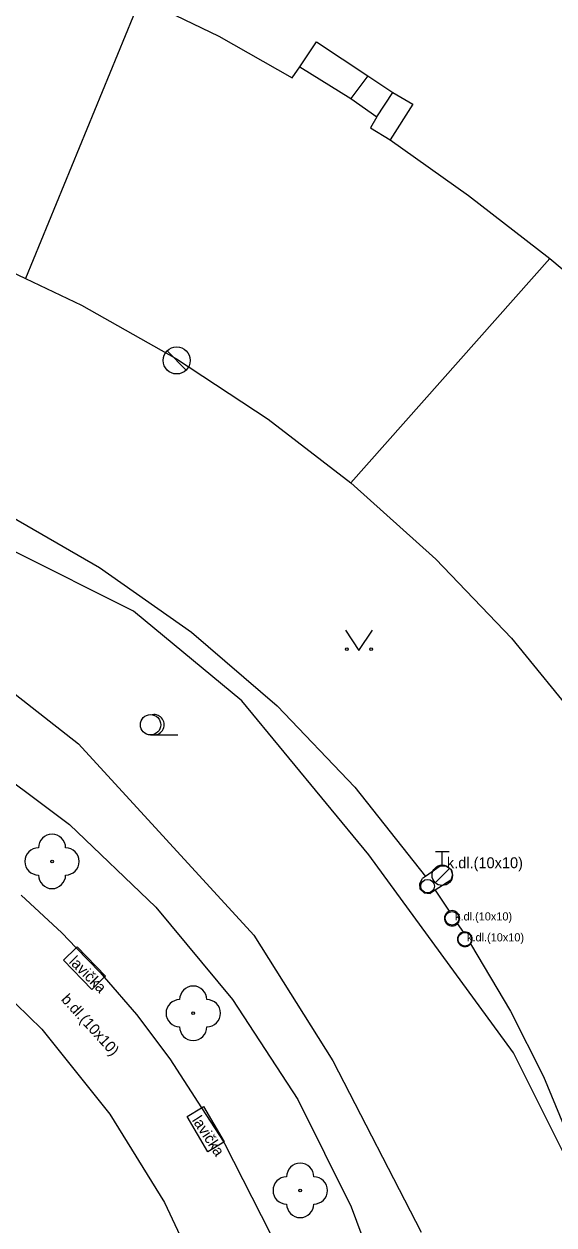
# Model space of a CAD drawing. Extents: x -600309 to -598967, y -1161267 to -1160292.
# Drawn here: x -599747.2 to -599727.72, y -1160585.2 to -1160541.07 of the extents above; entities that cross this region are included whole.
import ezdxf

# ---------------------------------------------------------------- set-up
doc = ezdxf.new("R2010")
doc.units = 0
for name, color, linetype in [('Level 11', 7, 'Continuous'), ('Level 22', 7, 'Continuous'), ('Level 27', 7, 'Continuous'), ('Level 28', 7, 'Continuous'), ('Level 36', 7, 'Continuous'), ('Level 40', 7, 'Continuous'), ('Level 42', 7, 'Continuous'), ('Level 5', 7, 'Continuous'), ('Level 53', 7, 'Continuous')]:
    doc.layers.add(name, color=color, linetype=linetype)

msp = doc.modelspace()

# ---------------------------------------------------------------- linework, layer by layer
at = {"layer": 'Level 11'}
for points in [[(-599737.06, -1160542.64), (-599736.45, -1160541.73)], [(-599736.45, -1160541.73), (-599734.57, -1160542.9699)], [(-599734.57, -1160542.9699), (-599735.19, -1160543.81)], [(-599734.57, -1160542.9699), (-599733.65, -1160543.59)], [(-599734.23, -1160544.48), (-599733.65, -1160543.59)], [(-599733.65, -1160543.59), (-599732.9099, -1160544.02)], [(-599732.9099, -1160544.02), (-599733.75, -1160545.32)], [(-599748.99, -1160558.41), (-599744.43, -1160561.04)], [(-599743.18, -1160562.65), (-599747.62, -1160560.42)], [(-599744.43, -1160561.04), (-599741.04, -1160563.42), (-599737.9, -1160566.12), (-599735.04, -1160569.11), (-599732.45, -1160572.39)], [(-599739.2, -1160565.94), (-599743.18, -1160562.65)], [(-599748.79, -1160564.71), (-599745.2, -1160567.52)], [(-599734.53, -1160571.6), (-599739.2, -1160565.94)], [(-599745.2, -1160567.52), (-599738.76, -1160574.55)], [(-599749.05, -1160567.85), (-599745.53, -1160570.49), (-599742.35, -1160573.52), (-599739.54, -1160576.91), (-599737.14, -1160580.59), (-599735.18, -1160584.53)], [(-599756.1, -1160570.82), (-599752.62, -1160572.8), (-599749.42, -1160575.21), (-599746.55, -1160578), (-599744.05, -1160581.13)], [(-599729.21, -1160578.88), (-599734.53, -1160571.6)], [(-599731.91, -1160572.01), (-599732.45, -1160572.39), (-599732.56, -1160572.47)], [(-599731.91, -1160572.01), (-599731.7, -1160572), (-599731.52, -1160572.12), (-599731.45, -1160572.33), (-599731.51, -1160572.53)], [(-599732.64, -1160572.86), (-599732.66, -1160572.65), (-599732.56, -1160572.47)], [(-599731.51, -1160572.53), (-599732.09, -1160572.9), (-599732.28, -1160573.02)], [(-599747.31, -1160573.08), (-599745.81, -1160574.46), (-599745.28, -1160575.01)], [(-599732.64, -1160572.86), (-599732.49, -1160573)], [(-599732.49, -1160573), (-599732.28, -1160573.02)], [(-599732.09, -1160572.9), (-599731.58, -1160573.67)], [(-599731.1898, -1160573.93), (-599731.1941, -1160573.8813), (-599731.2067, -1160573.8342), (-599731.2273, -1160573.7899), (-599731.2554, -1160573.7499), (-599731.2899, -1160573.7154), (-599731.3299, -1160573.6873), (-599731.3742, -1160573.6667), (-599731.4213, -1160573.6541), (-599731.47, -1160573.6498), (-599731.5187, -1160573.6541), (-599731.5658, -1160573.6667), (-599731.58, -1160573.67), (-599731.6101, -1160573.6873), (-599731.6501, -1160573.7154), (-599731.6846, -1160573.7499), (-599731.7127, -1160573.7899), (-599731.7333, -1160573.8342), (-599731.7459, -1160573.8813), (-599731.7502, -1160573.93), (-599731.7459, -1160573.9787), (-599731.7333, -1160574.0258), (-599731.7127, -1160574.0701), (-599731.6846, -1160574.1101), (-599731.6501, -1160574.1446), (-599731.6101, -1160574.1727), (-599731.5658, -1160574.1933), (-599731.5187, -1160574.2059), (-599731.47, -1160574.2102), (-599731.4213, -1160574.2059), (-599731.3742, -1160574.1933), (-599731.3299, -1160574.1727), (-599731.2899, -1160574.1446), (-599731.27, -1160574.13), (-599731.2554, -1160574.1101), (-599731.2273, -1160574.0701), (-599731.2067, -1160574.0258), (-599731.1941, -1160573.9787), (-599731.1898, -1160573.93)], [(-599731.27, -1160574.13), (-599731.06, -1160574.44)], [(-599738.76, -1160574.55), (-599735.85, -1160579.17)], [(-599730.7309, -1160574.7), (-599730.735, -1160574.6533), (-599730.7471, -1160574.608), (-599730.767, -1160574.5654), (-599730.7939, -1160574.527), (-599730.827, -1160574.4939), (-599730.8654, -1160574.467), (-599730.908, -1160574.4471), (-599730.9533, -1160574.435), (-599731, -1160574.4309), (-599731.06, -1160574.44), (-599731.092, -1160574.4471), (-599731.1345, -1160574.467), (-599731.173, -1160574.4939), (-599731.2061, -1160574.527), (-599731.233, -1160574.5654), (-599731.2529, -1160574.608), (-599731.265, -1160574.6533), (-599731.2691, -1160574.7), (-599731.265, -1160574.7467), (-599731.2529, -1160574.792), (-599731.233, -1160574.8345), (-599731.2061, -1160574.873), (-599731.173, -1160574.9061), (-599731.1345, -1160574.933), (-599731.092, -1160574.9529), (-599731.0467, -1160574.965), (-599731, -1160574.9691), (-599730.9533, -1160574.965), (-599730.908, -1160574.9529), (-599730.8654, -1160574.933), (-599730.827, -1160574.9061), (-599730.79, -1160574.87), (-599730.767, -1160574.8345), (-599730.7471, -1160574.792), (-599730.735, -1160574.7467), (-599730.7309, -1160574.7)], [(-599745.28, -1160575.01), (-599744.4, -1160575.92), (-599744.25, -1160576.1)], [(-599730.79, -1160574.87), (-599729.32, -1160577.34), (-599728.11, -1160579.74), (-599727.08, -1160582.23), (-599726.22, -1160584.81)], [(-599744.25, -1160576.1), (-599743.07, -1160577.47), (-599741.84, -1160579.09)], [(-599741.84, -1160579.09), (-599740.68, -1160580.89)], [(-599735.85, -1160579.17), (-599732.61, -1160585.47)], [(-599726.46, -1160584.39), (-599729.21, -1160578.88)], [(-599740.68, -1160580.89), (-599739.86, -1160582.16)], [(-599744.05, -1160581.13), (-599742.04, -1160584.37), (-599740.42, -1160587.82), (-599739.23, -1160591.44), (-599738.47, -1160595.18)], [(-599739.86, -1160582.16), (-599739.83, -1160582.2), (-599738.16, -1160585.5), (-599737.4, -1160587.53)], [(-599735.18, -1160584.53), (-599734.07, -1160587.5), (-599733.22, -1160590.55), (-599732.64, -1160593.66), (-599732.32, -1160596.81)]]:
    msp.add_lwpolyline(points, dxfattribs=at)
at = {"layer": 'Level 22'}
for centre in [(-599746.17, -1160571.84), (-599740.98, -1160577.42), (-599737.05, -1160583.93)]:
    msp.add_circle(centre, 0.05, dxfattribs=at)
for centre, start, end in [((-599746.17, -1160571.34), 0, 180), ((-599746.67, -1160571.84), 90, 270), ((-599745.67, -1160571.84), 270, 90), ((-599746.17, -1160572.34), 180, 0), ((-599740.98, -1160576.92), 0, 180), ((-599741.48, -1160577.42), 90, 270), ((-599740.48, -1160577.42), 270, 90), ((-599740.98, -1160577.92), 180, 0), ((-599737.05, -1160583.43), 0, 180), ((-599737.55, -1160583.93), 90, 270), ((-599736.55, -1160583.93), 270, 90), ((-599737.05, -1160584.43), 180, 0)]:
    msp.add_arc(centre, 0.5, start, end, dxfattribs=at)
at = {"layer": 'Level 27'}
msp.add_line((-599741.237, -1160553.784), (-599741.944, -1160553.077), dxfattribs=at)
msp.add_circle((-599741.59, -1160553.43), 0.5, dxfattribs=at)
at = {"layer": 'Level 28'}
for p, q in [((-599732.08, -1160571.475), (-599731.58, -1160571.475)), ((-599731.83, -1160571.975), (-599731.83, -1160571.475)), ((-599732.088, -1160572.622), (-599731.558, -1160572.092))]:
    msp.add_line(p, q, dxfattribs=at)
for centre, radius in [((-599731.83, -1160572.35), 0.375), ((-599732.37, -1160572.75), 0.25), ((-599731.47, -1160573.93), 0.25), ((-599731, -1160574.7), 0.25)]:
    msp.add_circle(centre, radius, dxfattribs=at)
at = {"layer": 'Level 36'}
msp.add_line((-599742.55, -1160567.195), (-599741.55, -1160567.195), dxfattribs=at)
msp.add_lwpolyline([(-599735.39, -1160563.34), (-599734.89, -1160564.09), (-599734.39, -1160563.34)], dxfattribs=at)
for centre, radius in [((-599735.3402, -1160564.0398), 0.05), ((-599734.4408, -1160564.0398), 0.05), ((-599742.55, -1160566.8196), 0.375)]:
    msp.add_circle(centre, radius, dxfattribs=at)
msp.add_arc((-599742.425, -1160566.8196), 0.375, 260.40593, 99.59407, dxfattribs=at)
at = {"layer": 'Level 5'}
for points in [[(-599742.92, -1160540.12), (-599747.15, -1160550.42)], [(-599742.92, -1160540.12), (-599740.04, -1160541.52)], [(-599740.04, -1160541.52), (-599737.35, -1160543.05)], [(-599737.35, -1160543.05), (-599737.06, -1160542.64)], [(-599737.06, -1160542.64), (-599735.19, -1160543.81)], [(-599735.19, -1160543.81), (-599734.23, -1160544.48)], [(-599734.23, -1160544.48), (-599734.4699, -1160544.88)], [(-599734.4699, -1160544.88), (-599733.75, -1160545.32)], [(-599733.75, -1160545.32), (-599730.86, -1160547.37)], [(-599730.86, -1160547.37), (-599727.88, -1160549.69)], [(-599748.72, -1160549.68), (-599747.15, -1160550.42), (-599745.09, -1160551.4), (-599741.59, -1160553.37)], [(-599727.88, -1160549.69), (-599735.19, -1160557.93)], [(-599727.88, -1160549.69), (-599724.87, -1160552.21)], [(-599741.59, -1160553.37), (-599738.23, -1160555.59), (-599735.19, -1160557.93)], [(-599735.19, -1160557.93), (-599732.07, -1160560.73), (-599729.29, -1160563.64), (-599726.75, -1160566.75), (-599725.61, -1160568.37), (-599724.45, -1160570.04)]]:
    msp.add_lwpolyline(points, dxfattribs=at)
at = {"layer": 'Level 53'}
for points in [[(-599745.75, -1160575.47), (-599745.28, -1160575.01)], [(-599745.28, -1160575.01), (-599745.25, -1160574.98)], [(-599745.25, -1160574.98), (-599744.21, -1160576.06)], [(-599744.71, -1160576.55), (-599745.75, -1160575.47)], [(-599744.25, -1160576.1), (-599744.71, -1160576.55)], [(-599744.21, -1160576.06), (-599744.25, -1160576.1)], [(-599741.21, -1160581.21), (-599740.68, -1160580.89)], [(-599740.68, -1160580.89), (-599740.61, -1160580.85)], [(-599740.61, -1160580.85), (-599739.84, -1160582.15)], [(-599740.44, -1160582.51), (-599741.21, -1160581.21)], [(-599739.86, -1160582.16), (-599740.44, -1160582.51)], [(-599739.84, -1160582.15), (-599739.86, -1160582.16)]]:
    msp.add_lwpolyline(points, dxfattribs=at)

# ---------------------------------------------------------------- texts
at = {"layer": 'Level 40'}
for height, p in [(0.4, (-599731.66, -1160572.09)), (0.3, (-599731.36, -1160574.01)), (0.3, (-599730.92, -1160574.78))]:
    msp.add_text('k.dl.(10x10)', height=height, dxfattribs=at).set_placement(p)
msp.add_text('b.dl.(10x10)', height=0.4, rotation=312.35, dxfattribs=at).set_placement((-599745.86, -1160576.93))
at = {"layer": 'Level 42'}
for rotation, p in [(315.02, (-599745.57, -1160575.55)), (303.3, (-599741.04, -1160581.35))]:
    msp.add_text('lavička', height=0.4, rotation=rotation, dxfattribs=at).set_placement(p)

doc.saveas('drawing.dxf')
